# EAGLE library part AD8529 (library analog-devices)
8 MHz Rail-to-Rail Operational Amplifiers Source: http://www.analog.com/static/imported-files/data_sheets/AD8519_8529.pdf
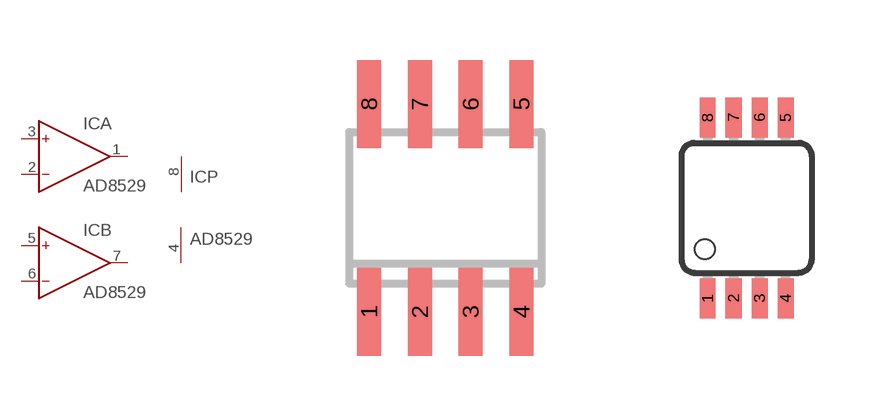
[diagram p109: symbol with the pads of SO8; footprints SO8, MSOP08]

Designator prefix IC; gates A=OP B=OP P=PWR+-

## AD8529R (MF: ALTERA CORPORATION; MPN: AD8529ARZ; OC_FARNELL: unknown; OC_NEWARK: 59K6807)  [SO8]
1  A:OUT  out
2  A:IN-  in
3  A:IN+  in
4  P:V-  pwr
5  B:IN+  in
6  B:IN-  in
7  B:OUT  out
8  P:V+  pwr

## AD8529RM (OC_FARNELL: 1424141; OC_NEWARK: unknown)  [MSOP08]
Pads as for SO8

## Footprint SO8 (pad centres in mm)
8-Lead Small Outline IC (SO-8) Source: http://www.analog.com/UploadedFiles/Data_Sheets/703465986AD8611_2_0.pdf
smd 0.6 x 2.2: 1 -1.905,-2.6; 2 -0.635,-2.6; 3 0.635,-2.6; 4 1.905,-2.6; 5 1.905,2.6; 6 0.635,2.6; 7 -0.635,2.6; 8 -1.905,2.6

## Footprint MSOP08 (pad centres in mm)
8-Lead micro SO (RM-8) Source: http://www.analog.com/UploadedFiles/Data_Sheets/703465986AD8611_2_0.pdf
smd 0.4 x 1: 1 -0.976,-2.263; 2 -0.326,-2.263; 3 0.324,-2.263; 4 0.974,-2.263; 5 0.974,2.262; 6 0.324,2.262; 7 -0.326,2.262; 8 -0.976,2.262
